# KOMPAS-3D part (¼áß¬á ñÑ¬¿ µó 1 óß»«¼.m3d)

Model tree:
1. Эскиз:1
2. Операция выдавливания:24
     Толщина стенки 2 = 14; Расстояние 1 = 0.6
3. Эскиз:22
4. Операция выдавливания:25
     Толщина стенки 1 = 7; Толщина стенки 2 = 6; Расстояние 1 = 0.6; Расстояние 2 = 0.6
5. Эскиз:23
6. Операция выдавливания:26
     Толщина стенки 1 = 6; Толщина стенки 2 = 6; Расстояние 1 = 0.6
7. Эскиз:26
8. Вырезать элемент выдавливания:3
     Толщина стенки 1 = 7; Расстояние 1 = 10
